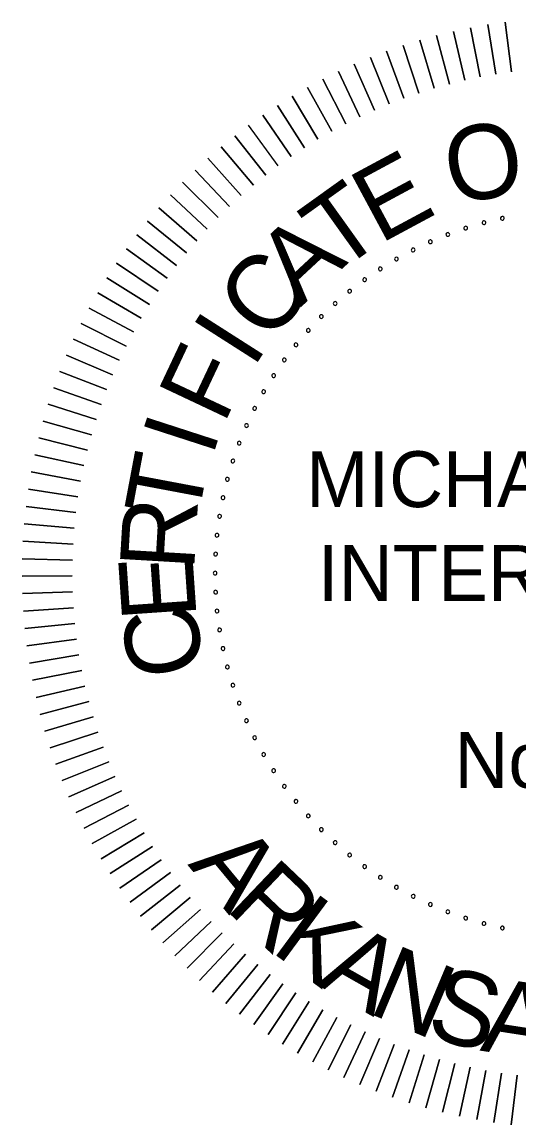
# Model space of a CAD drawing. Extents: x -24122 to 24238, y -8840 to 11381.
# Drawn here: x 10547 to 11660, y -8831 to -6362 of the extents above; entities that cross this region are included whole.
import ezdxf

# ---------------------------------------------------------------- set-up
doc = ezdxf.new("R2010")
doc.units = 0
doc.layers.add('G-ANNO-TEXT', color=7, linetype='Continuous')

msp = doc.modelspace()

# ---------------------------------------------------------------- linework, layer by layer
at = {"layer": 'G-ANNO-TEXT'}
for points in [[(11608.5, -6478.2), (11590.4, -6367.5)], [(11590.4, -6367.5), (11608.5, -6478.2)], [(11643.7, -6473), (11629, -6361.8)], [(11629, -6361.8), (11643.7, -6473)], [(11504.2, -6500.5), (11475.7, -6391.9)], [(11475.7, -6391.9), (11504.2, -6500.5)], [(11538.8, -6492), (11513.7, -6382.6)], [(11513.7, -6382.6), (11538.8, -6492)], [(11573.5, -6484.6), (11551.9, -6374.4)], [(11551.9, -6374.4), (11573.5, -6484.6)], [(11436, -6520.7), (11400.8, -6414.1)], [(11400.8, -6414.1), (11436, -6520.7)], [(11470, -6510), (11438.1, -6402.4)], [(11438.1, -6402.4), (11470, -6510)], [(11369.2, -6545.2), (11327.4, -6441)], [(11327.4, -6441), (11369.2, -6545.2)], [(11402.4, -6532.4), (11363.8, -6427)], [(11363.8, -6427), (11402.4, -6532.4)], [(11336.5, -6558.9), (11291.3, -6456.2)], [(11291.3, -6456.2), (11336.5, -6558.9)], [(11272.3, -6589.6), (11220.8, -6489.9)], [(11220.8, -6489.9), (11272.3, -6589.6)], [(11304.1, -6573.8), (11255.8, -6472.5)], [(11255.8, -6472.5), (11304.1, -6573.8)], [(11240.9, -6606.4), (11186.3, -6508.4)], [(11186.3, -6508.4), (11240.9, -6606.4)], [(11210.1, -6624.2), (11152.5, -6527.9)], [(11152.5, -6527.9), (11210.1, -6624.2)], [(11179.9, -6643), (11119.3, -6548.5)], [(11119.3, -6548.5), (11179.9, -6643)], [(11150.3, -6662.6), (11086.7, -6570.2)], [(11086.7, -6570.2), (11150.3, -6662.6)], [(11093, -6704.8), (11023.7, -6616.5)], [(11023.7, -6616.5), (11093, -6704.8)], [(11121.3, -6683.3), (11054.8, -6592.8)], [(11065.4, -6727.2), (10993.3, -6641.1)], [(10993.3, -6641.1), (11065.4, -6727.2)], [(11038.4, -6750.4), (10963.8, -6666.6)], [(10963.8, -6666.6), (11038.4, -6750.4)], [(11012.3, -6774.5), (10935, -6693.1)], [(10935, -6693.1), (11012.3, -6774.5)], [(10986.9, -6799.4), (10907.1, -6720.5)], [(10907.1, -6720.5), (10986.9, -6799.4)], [(10962.3, -6825.1), (10880, -6748.7)], [(10880, -6748.7), (10962.3, -6825.1)], [(10938.5, -6851.5), (10853.9, -6777.8)], [(10853.9, -6777.8), (10938.5, -6851.5)], [(10915.5, -6878.7), (10828.6, -6807.6)], [(10828.6, -6807.6), (10915.5, -6878.7)], [(10893.4, -6906.6), (10804.4, -6838.3)], [(10804.4, -6838.3), (10893.4, -6906.6)], [(10872.2, -6935.1), (10781.1, -6869.7)], [(10781.1, -6869.7), (10872.2, -6935.1)], [(10851.9, -6964.3), (10758.8, -6901.8)], [(10758.8, -6901.8), (10851.9, -6964.3)], [(10832.6, -6994.2), (10737.5, -6934.6)], [(10737.5, -6934.6), (10832.6, -6994.2)], [(10814.2, -7024.6), (10717.3, -6968)], [(10717.3, -6968), (10814.2, -7024.6)], [(10796.7, -7055.6), (10698.1, -7002.1)], [(10698.1, -7002.1), (10796.7, -7055.6)], [(10780.3, -7087.1), (10680, -7036.7)], [(10680, -7036.7), (10780.3, -7087.1)], [(10764.8, -7119.1), (10663, -7071.9)], [(10663, -7071.9), (10764.8, -7119.1)], [(10750.3, -7151.6), (10647.1, -7107.6)], [(10647.1, -7107.6), (10750.3, -7151.6)], [(10736.9, -7184.6), (10632.3, -7143.8)], [(10632.3, -7143.8), (10736.9, -7184.6)], [(10724.5, -7217.9), (10618.7, -7180.5)], [(10618.7, -7180.5), (10724.5, -7217.9)], [(10713.2, -7251.6), (10606.3, -7217.5)], [(10606.3, -7217.5), (10713.2, -7251.6)], [(10702.9, -7285.7), (10595, -7255)], [(10595, -7255), (10702.9, -7285.7)], [(10693.7, -7320), (10584.9, -7292.7)], [(10584.9, -7292.7), (10693.7, -7320)], [(10685.6, -7354.7), (10576, -7330.8)], [(10576, -7330.8), (10685.6, -7354.7)], [(10678.6, -7389.5), (10568.2, -7369.1)], [(10568.2, -7369.1), (10678.6, -7389.5)], [(10672.7, -7424.6), (10561.7, -7407.7)], [(10561.7, -7407.7), (10672.7, -7424.6)], [(10667.9, -7459.9), (10556.4, -7446.4)], [(10556.4, -7446.4), (10667.9, -7459.9)], [(10664.2, -7495.2), (10552.4, -7485.3)], [(10552.4, -7485.3), (10664.2, -7495.2)], [(10661.6, -7530.7), (10549.5, -7524.3)], [(10549.5, -7524.3), (10661.6, -7530.7)], [(10660.1, -7566.2), (10547.9, -7563.3)], [(10547.9, -7563.3), (10660.1, -7566.2)], [(10659.7, -7601.8), (10547.5, -7602.4)], [(10547.5, -7602.4), (10659.7, -7601.8)], [(10660.5, -7637.4), (10548.3, -7641.5)], [(10548.3, -7641.5), (10660.5, -7637.4)], [(10662.4, -7672.9), (10550.4, -7680.5)], [(10550.4, -7680.5), (10662.4, -7672.9)], [(10665.3, -7708.3), (10553.7, -7719.5)], [(10553.7, -7719.5), (10665.3, -7708.3)], [(10669.4, -7743.7), (10558.2, -7758.3)], [(10558.2, -7758.3), (10669.4, -7743.7)], [(10674.6, -7778.8), (10563.9, -7797)], [(10563.9, -7797), (10674.6, -7778.8)], [(10681, -7813.8), (10570.8, -7835.5)], [(10570.8, -7835.5), (10681, -7813.8)], [(10688.4, -7848.6), (10579, -7873.7)], [(10579, -7873.7), (10688.4, -7848.6)], [(10696.9, -7883.2), (10588.3, -7911.7)], [(10588.3, -7911.7), (10696.9, -7883.2)], [(10706.4, -7917.4), (10598.8, -7949.3)], [(10598.8, -7949.3), (10706.4, -7917.4)], [(10717.1, -7951.4), (10610.5, -7986.6)], [(10610.5, -7986.6), (10717.1, -7951.4)], [(10728.8, -7984.9), (10623.4, -8023.5)], [(10623.4, -8023.5), (10728.8, -7984.9)], [(10741.5, -8018.1), (10637.4, -8060)], [(10637.4, -8060), (10741.5, -8018.1)], [(10755.3, -8050.9), (10652.6, -8096.1)], [(10652.6, -8096.1), (10755.3, -8050.9)], [(10770.2, -8083.3), (10668.9, -8131.6)], [(10668.9, -8131.6), (10770.2, -8083.3)], [(10786, -8115.1), (10686.3, -8166.6)], [(10686.3, -8166.6), (10786, -8115.1)], [(10802.8, -8146.4), (10704.8, -8201.1)], [(10704.8, -8201.1), (10802.8, -8146.4)], [(10820.6, -8177.2), (10724.3, -8234.9)], [(10724.3, -8234.9), (10820.6, -8177.2)], [(10839.3, -8207.5), (10744.9, -8268.1)], [(10744.9, -8268.1), (10839.3, -8207.5)], [(10859, -8237.1), (10766.6, -8300.7)], [(10766.6, -8300.7), (10859, -8237.1)], [(10879.7, -8266.1), (10789.2, -8332.5)], [(10789.2, -8332.5), (10879.7, -8266.1)], [(10901.2, -8294.4), (10812.9, -8363.7)], [(10812.9, -8363.7), (10901.2, -8294.4)], [(10923.6, -8322), (10837.5, -8394)], [(10837.5, -8394), (10923.6, -8322)], [(10946.8, -8348.9), (10863, -8423.6)], [(10863, -8423.6), (10946.8, -8348.9)], [(10970.9, -8375.1), (10889.5, -8452.4)], [(10889.5, -8452.4), (10970.9, -8375.1)], [(10995.8, -8400.5), (10916.9, -8480.3)], [(10916.9, -8480.3), (10995.8, -8400.5)], [(11021.5, -8425.1), (10945.1, -8507.4)], [(10945.1, -8507.4), (11021.5, -8425.1)], [(10974.2, -8533.5), (11047.9, -8448.9)], [(11047.9, -8448.9), (10974.2, -8533.5)], [(11004, -8558.7), (11075.1, -8471.9)], [(11075.1, -8471.9), (11004, -8558.7)], [(11034.7, -8583), (11103, -8493.9)], [(11103, -8493.9), (11034.7, -8583)], [(11066.1, -8606.3), (11131.5, -8515.1)], [(11131.5, -8515.1), (11066.1, -8606.3)], [(11098.2, -8628.6), (11160.7, -8535.4)], [(11160.7, -8535.4), (11098.2, -8628.6)], [(11131, -8649.9), (11190.6, -8554.8)], [(11190.6, -8554.8), (11131, -8649.9)], [(11164.4, -8670.1), (11221, -8573.2)], [(11221, -8573.2), (11164.4, -8670.1)], [(11198.5, -8689.3), (11252, -8590.7)], [(11252, -8590.7), (11198.5, -8689.3)], [(11233.1, -8707.4), (11283.5, -8607.1)], [(11283.5, -8607.1), (11233.1, -8707.4)], [(11268.3, -8724.4), (11315.5, -8622.6)], [(11315.5, -8622.6), (11268.3, -8724.4)], [(11304, -8740.3), (11348, -8637.1)], [(11348, -8637.1), (11304, -8740.3)], [(11340.2, -8755.1), (11381, -8650.5)], [(11381, -8650.5), (11340.2, -8755.1)], [(11376.9, -8768.7), (11414.3, -8662.9)], [(11414.3, -8662.9), (11376.9, -8768.7)], [(11413.9, -8781.1), (11448, -8674.2)], [(11448, -8674.2), (11413.9, -8781.1)], [(11451.4, -8792.4), (11482.1, -8684.5)], [(11482.1, -8684.5), (11451.4, -8792.4)], [(11489.1, -8802.5), (11516.4, -8693.7)], [(11516.4, -8693.7), (11489.1, -8802.5)], [(11527.2, -8811.4), (11551.1, -8701.8)], [(11551.1, -8701.8), (11527.2, -8811.4)], [(11565.5, -8819.1), (11585.9, -8708.8)], [(11585.9, -8708.8), (11565.5, -8819.1)], [(11604.1, -8825.6), (11621, -8714.7)], [(11621, -8714.7), (11604.1, -8825.6)], [(11642.8, -8830.9), (11656.3, -8719.5)], [(11656.3, -8719.5), (11642.8, -8830.9)]]:
    msp.add_lwpolyline(points, dxfattribs=at)
for centre, start, end in [((11581.7, -6811), 15, 195), ((11581.7, -6811), 195, 15), ((11623, -6801.1), 12, 192), ((11623, -6801.1), 192, 12), ((11500.8, -6837.3), 21, 201), ((11500.8, -6837.3), 201, 21), ((11540.9, -6823.1), 18, 198), ((11540.9, -6823.1), 198, 18), ((11461.6, -6853.6), 24, 204), ((11461.6, -6853.6), 204, 24), ((11385.8, -6892.2), 30, 210), ((11423.2, -6871.9), 27, 207), ((11423.2, -6871.9), 207, 27), ((11349.6, -6914.4), 33, 213), ((11349.6, -6914.4), 213, 33), ((11385.8, -6892.2), 210, 30), ((11314.5, -6938.5), 36, 216), ((11314.5, -6938.5), 216, 36), ((11280.8, -6964.3), 39, 219), ((11280.8, -6964.3), 219, 39), ((11248.5, -6991.9), 42, 222), ((11248.5, -6991.9), 222, 42), ((11217.6, -7021.2), 45, 225), ((11217.6, -7021.2), 225, 45), ((11188.3, -7052.1), 48, 228), ((11188.3, -7052.1), 228, 48), ((11160.7, -7084.4), 51, 231), ((11160.7, -7084.4), 231, 51), ((11134.8, -7118.1), 54, 234), ((11134.8, -7118.1), 234, 54), ((11110.8, -7153.2), 57, 237), ((11110.8, -7153.2), 237, 57), ((11088.5, -7189.4), 60, 240), ((11088.5, -7189.4), 240, 60), ((11068.3, -7226.8), 63, 243), ((11068.3, -7226.8), 243, 63), ((11050, -7265.2), 66, 246), ((11050, -7265.2), 246, 66), ((11033.7, -7304.4), 69, 249), ((11033.7, -7304.4), 249, 69), ((11019.5, -7344.5), 72, 252), ((11019.5, -7344.5), 252, 72), ((11007.4, -7385.3), 75, 255), ((11007.4, -7385.3), 255, 75), ((10997.5, -7426.6), 78, 258), ((10997.5, -7426.6), 258, 78), ((10989.7, -7468.4), 81, 261), ((10989.7, -7468.4), 261, 81), ((10984.2, -7510.6), 84, 264), ((10984.2, -7510.6), 264, 84), ((10980.9, -7553), 87, 267), ((10980.9, -7553), 267, 87), ((10979.7, -7595.5), 90, 270), ((10979.7, -7595.5), 270, 90), ((10980.9, -7638), 93, 273), ((10980.9, -7638), 273, 93), ((10984.2, -7680.4), 96, 276), ((10984.2, -7680.4), 276, 96), ((10989.7, -7722.5), 99, 279), ((10989.7, -7722.5), 279, 99), ((10997.5, -7764.3), 102, 282), ((10997.5, -7764.3), 282, 102), ((11007.4, -7805.7), 105, 285), ((11007.4, -7805.7), 285, 105), ((11019.5, -7846.5), 108, 288), ((11019.5, -7846.5), 288, 108), ((11033.7, -7886.5), 111, 291), ((11033.7, -7886.5), 291, 111), ((11050, -7925.8), 114, 294), ((11050, -7925.8), 294, 114), ((11068.3, -7964.2), 117, 297), ((11068.3, -7964.2), 297, 117), ((11088.5, -8001.6), 120, 300), ((11088.5, -8001.6), 300, 120), ((11110.8, -8037.8), 123, 303), ((11110.8, -8037.8), 303, 123), ((11134.8, -8072.9), 126, 306), ((11134.8, -8072.9), 306, 126), ((11160.7, -8106.6), 129, 309), ((11160.7, -8106.6), 309, 129), ((11188.3, -8138.9), 132, 312), ((11188.3, -8138.9), 312, 132), ((11217.6, -8169.8), 135, 315), ((11217.6, -8169.8), 315, 135), ((11248.5, -8199), 138, 318), ((11248.5, -8199), 318, 138), ((11280.8, -8226.6), 141, 321), ((11280.8, -8226.6), 321, 141), ((11314.5, -8252.5), 144, 324), ((11314.5, -8252.5), 324, 144), ((11349.6, -8276.6), 147, 327), ((11349.6, -8276.6), 327, 147), ((11385.8, -8298.8), 330, 150), ((11385.8, -8298.8), 150, 330), ((11423.2, -8319.1), 153, 333), ((11423.2, -8319.1), 333, 153), ((11461.6, -8337.4), 156, 336), ((11461.6, -8337.4), 336, 156), ((11500.8, -8353.7), 159, 339), ((11500.8, -8353.7), 339, 159), ((11540.9, -8367.9), 162, 342), ((11540.9, -8367.9), 342, 162), ((11581.7, -8380), 165, 345), ((11581.7, -8380), 345, 165), ((11623, -8389.9), 168, 348), ((11623, -8389.9), 348, 168)]:
    msp.add_arc(centre, 4.17, start, end, dxfattribs=at)

# ---------------------------------------------------------------- texts
for s, rotation, p in [('O', 10.7295, (11510.3, -6772.2)), ('E', 28.279, (11348.5, -6859.6)), ('T', 35.5725, (11255.4, -6924.1)), ('A', 42.8659, (11170.8, -7001.1)), ('C', 50.1594, (11100.6, -7084.4)), ('I', 57.4529, (11064.4, -7140.1)), ('F', 64.7464, (10999, -7264.8)), ('I', 72.0398, (10973.2, -7338)), ('T', 79.3333, (10940.1, -7481.6)), ('R', 86.6268, (10932.4, -7591.8)), ('E', 93.9203, (10938.6, -7695.9)), ('C', 101.2137, (10959.9, -7811.8)), ('A', 309.5859, (10917.2, -8248.1)), ('R', 316.3356, (11000, -8346.4)), ('K', 323.6428, (11101.9, -8441)), ('A', 330.3925, (11206.1, -8516.3)), ('N', 337.1422, (11318.4, -8578.7)), ('S', 344.4494, (11447.3, -8631)), ('A', 351.1991, (11571.4, -8664.3))]:
    msp.add_text(s, height=166.7, rotation=rotation, dxfattribs=at).set_placement(p)
for s, height, p in [('MICHAEL BAKER', 125.016, (11183.6, -7447.7)), (' INTERNATIONAL', 125.016, (11163.5, -7657.9)), (' No. 1126', 125.02, (11469.2, -8076.5))]:
    msp.add_text(s, height=height, dxfattribs=at).set_placement(p)

doc.saveas('drawing.dxf')
